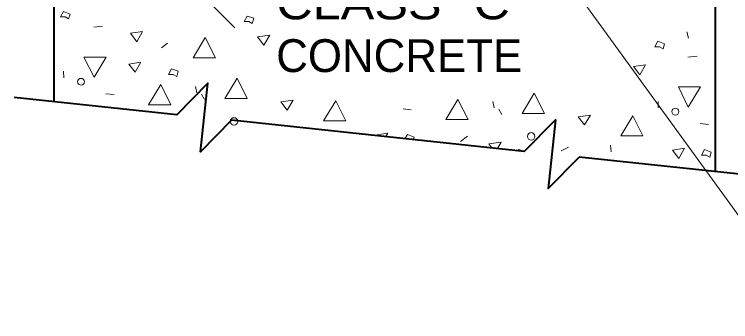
# Model space of a CAD drawing. Extents: x 312583 to 312854, y 144419 to 144597.
# Drawn here: x 312632.86 to 312649.47, y 144454.9 to 144462.01 of the extents above; entities that cross this region are included whole.
import ezdxf

# ---------------------------------------------------------------- set-up
doc = ezdxf.new("R2010")
doc.units = 0
doc.header["$LTSCALE"] = 0.3
doc.layers.add('1', color=7, linetype='Continuous', lineweight=13)

msp = doc.modelspace()

# ---------------------------------------------------------------- linework, layer by layer
at = {"layer": '1', "lineweight": 40}
for p, q in [((312649.1094, 144472.9434), (312649.1094, 144458.3767)), ((312633.776, 144463.2297), (312633.776, 144459.9867)), ((312644.6857, 144458.8367), (312637.9007, 144459.5574)), ((312650.152, 144458.2617), (312645.9584, 144458.7064))]:
    msp.add_line(p, q, dxfattribs=at)
at = {"layer": '1'}
for p, q in [((312637.9774, 144461.6964), (312634.581, 144465.0927)), ((312634.9107, 144461.7347), (312634.7037, 144461.7117)), ((312648.4577, 144461.6044), (312648.496, 144461.4587)), ((312636.4134, 144461.3437), (312636.2754, 144461.2364)), ((312648.6954, 144461.0447), (312648.4807, 144461.0217)), ((312634.006, 144460.6921), (312634.0137, 144460.5387)), ((312637.065, 144460.3394), (312637.0957, 144460.1937)), ((312634.9874, 144460.1707), (312635.179, 144460.1554)), ((312637.203, 144460.1631), (312637.272, 144460.0404)), ((312643.9574, 144459.9944), (312643.988, 144459.8487)), ((312647.7907, 144459.9944), (312647.7907, 144459.8487)), ((312641.8797, 144459.8257), (312642.0637, 144459.8027)), ((312644.0954, 144459.8181), (312644.1644, 144459.6954)), ((312648.7644, 144459.4807), (312648.956, 144459.4577)), ((312641.228, 144459.2124), (312641.2434, 144459.2047)), ((312642.7077, 144459.0667), (312642.7077, 144459.0514)), ((312643.367, 144459.1894), (312643.206, 144459.0667)), ((312643.8654, 144459.0131), (312643.9344, 144458.9211)), ((312645.713, 144458.9364), (312645.5444, 144458.8521)), ((312646.6867, 144458.9824), (312646.702, 144458.8291))]:
    msp.add_line(p, q, dxfattribs=at)
for points in [[(312652.6207, 144454.8961), (312651.44, 144454.8961), (312642.999, 144466.5111)], [(312641.4734, 144459.1817), (312641.5194, 144459.2584), (312641.228, 144459.2124)], [(312642.1097, 144459.1127), (312642.1327, 144459.1664), (312641.9794, 144459.2277), (312641.9257, 144459.1357)], [(312644.0647, 144458.9057), (312644.149, 144459.0514), (312643.8654, 144459.0131)], [(312644.6704, 144458.8444), (312644.563, 144458.8827), (312644.5477, 144458.8597)]]:
    msp.add_lwpolyline(points, dxfattribs=at)
for points in [[(312634.0444, 144461.9494), (312634.121, 144461.9034), (312634.1594, 144462.0184), (312634.006, 144462.0797), (312633.937, 144461.9494)], [(312638.2994, 144461.8421), (312638.376, 144461.7961), (312638.4144, 144461.9187), (312638.261, 144461.9724), (312638.192, 144461.8421)], [(312635.5547, 144461.5737), (312635.7004, 144461.3744), (312635.8384, 144461.6121)], [(312637.0114, 144461.0064), (312637.525, 144461.0064), (312637.2874, 144461.4741)], [(312638.4987, 144461.4894), (312638.6444, 144461.2977), (312638.79, 144461.5277)], [(312647.8214, 144461.2594), (312647.9057, 144461.2134), (312647.9364, 144461.3284), (312647.783, 144461.3897), (312647.714, 144461.2594)], [(312634.995, 144461.0217), (312634.4737, 144461.0217), (312634.7114, 144460.5541)], [(312635.5164, 144460.8607), (312635.662, 144460.6691), (312635.8, 144460.9067)], [(312636.5437, 144460.6154), (312636.628, 144460.5694), (312636.6587, 144460.6921), (312636.5054, 144460.7457), (312636.4364, 144460.6154)], [(312647.2157, 144460.8071), (312647.3614, 144460.6077), (312647.4994, 144460.8454)], [(312635.9764, 144459.9177), (312636.49, 144459.9177), (312636.26, 144460.3854)], [(312637.7474, 144460.0634), (312638.261, 144460.0634), (312638.031, 144460.5311)], [(312648.772, 144460.3317), (312648.2584, 144460.3317), (312648.4884, 144459.8641)], [(312642.8687, 144459.5727), (312643.3824, 144459.5727), (312643.1447, 144460.0404)], [(312644.6397, 144459.7184), (312645.1534, 144459.7184), (312644.9157, 144460.1861)], [(312639.043, 144459.9867), (312639.1887, 144459.7951), (312639.3267, 144460.0251)], [(312640.032, 144459.5421), (312640.5457, 144459.5421), (312640.3157, 144460.0097)], [(312645.9354, 144459.6417), (312646.081, 144459.4501), (312646.219, 144459.6801)], [(312646.9244, 144459.1971), (312647.438, 144459.1971), (312647.2004, 144459.6647)], [(312648.1204, 144458.8674), (312648.266, 144458.6757), (312648.404, 144458.9134)], [(312648.9024, 144458.7524), (312648.9867, 144458.7064), (312649.0174, 144458.8214), (312648.864, 144458.8827), (312648.795, 144458.7524)]]:
    msp.add_lwpolyline(points, close=True, dxfattribs=at)
at = {"layer": '1', "lineweight": 40}
for points in [[(312637.9007, 144459.5574), (312637.18, 144458.8291), (312637.3487, 144460.4161), (312636.628, 144459.6877), (312632.8637, 144460.0864)], [(312644.6857, 144458.8367), (312645.4064, 144459.5651), (312645.2377, 144457.9781), (312645.9584, 144458.7064)]]:
    msp.add_lwpolyline(points, dxfattribs=at)
at = {"layer": '1'}
for centre, radius in [((312634.41, 144460.4498), 0.0784), ((312648.1878, 144459.7587), 0.0784), ((312637.9562, 144459.5315), 0.0865), ((312644.8451, 144459.1859), 0.0865)]:
    msp.add_circle(centre, radius, dxfattribs=at)

# ---------------------------------------------------------------- texts
at = {"layer": '1', "width": 1.15}
msp.add_text('CLASS "C"', height=0.76, dxfattribs=at).set_placement((312638.9357, 144461.8947))
at = {"layer": '1'}
msp.add_text('CONCRETE', height=0.76, dxfattribs=at).set_placement((312638.9357, 144460.6747))

doc.saveas('drawing.dxf')
